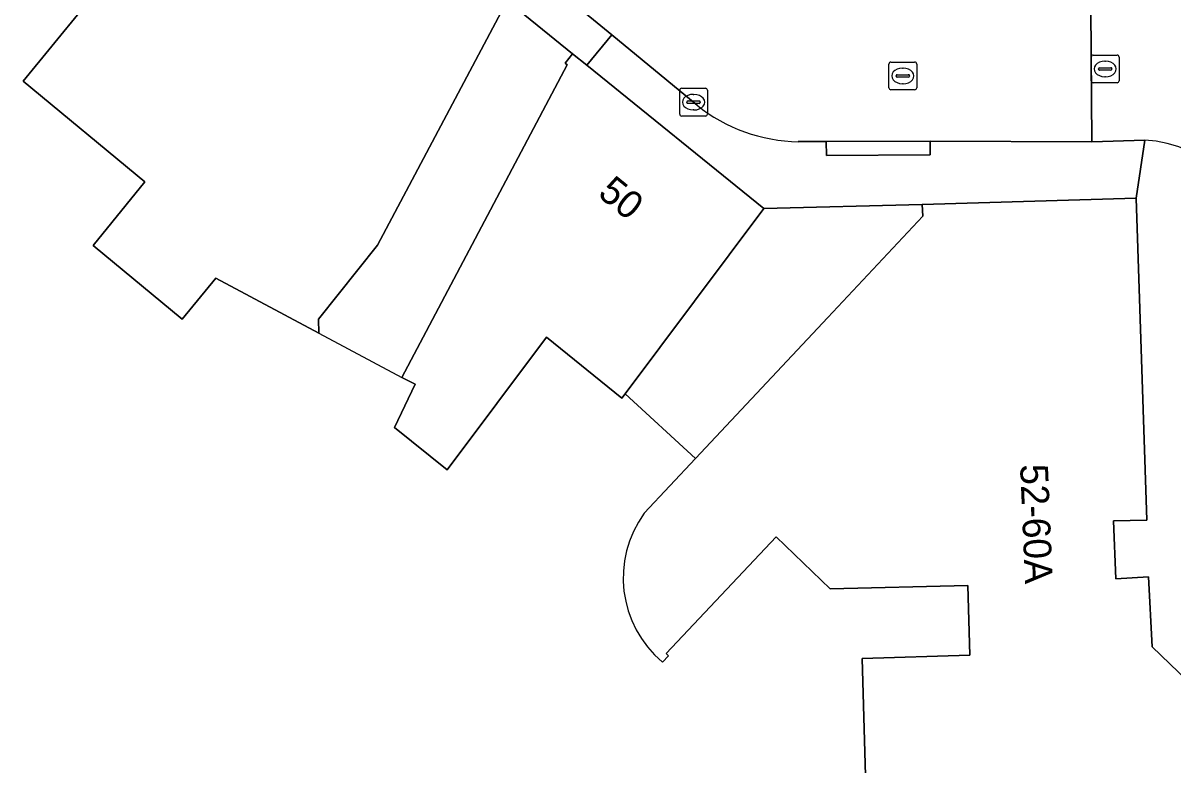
# Model space of a CAD drawing. Extents: x 161881 to 162523, y 381678 to 382381.
# Drawn here: x 162044.54 to 162085.93, y 382190.07 to 382216.77 of the extents above; entities that cross this region are included whole.
import ezdxf

# ---------------------------------------------------------------- set-up
doc = ezdxf.new("R2010")
doc.units = 0
for name, color, linetype in [('IMGEO_Erf', 7, 'Continuous'), ('IMGEO_Kolk', 7, 'Continuous'), ('IMGEO_Pand', 7, 'Continuous'), ('IMGEO_Pand_nummerreeks', 7, 'Continuous'), ('IMGEO_Pand_overbouw', 7, 'Continuous'), ('IMGEO_Rijbaan_lokaal_open', 7, 'Continuous'), ('IMGEO_Rioolput', 7, 'Continuous'), ('IMGEO_Voetpad_open', 7, 'Continuous')]:
    doc.layers.add(name, color=color, linetype=linetype)

msp = doc.modelspace()

# ---------------------------------------------------------------- linework, layer by layer
at = {"layer": 'IMGEO_Erf'}
for points in [[(162066.905, 382199.132), (162068.746, 382201.096), (162073.507, 382206.176), (162076.926, 382209.823), (162076.911, 382210.239), (162071.206, 382210.089), (162066.216, 382203.42), (162066.102, 382203.268), (162063.389, 382205.467), (162059.806, 382200.687), (162057.917, 382202.218), (162058.664, 382203.774), (162058.181, 382204.01), (162064.13, 382215.264), (162064.051, 382215.323), (162064.317, 382215.661), (162061.973, 382217.567), (162057.305, 382208.775), (162055.176, 382206.114), (162055.195, 382205.609), (162051.479, 382207.592), (162050.274, 382206.114), (162047.066, 382208.763), (162048.931, 382211.049), (162044.544, 382214.673), (162047.748, 382218.602)], [(162074.741, 382193.897), (162078.626, 382194.019), (162078.546, 382196.531), (162073.593, 382196.41), (162071.649, 382198.284), (162067.692, 382194.083), (162067.774, 382193.996), (162067.56, 382193.772)], [(162075.168, 382179.155), (162074.741, 382193.897)]]:
    msp.add_lwpolyline(points, dxfattribs=at)
msp.add_arc((162070.096, 382196.802), 3.951, 143.8643, 230.0699, dxfattribs=at)
at = {"layer": 'IMGEO_Kolk'}
for p, q in [((162068.178, 382213.495), (162068.178, 382214.347)), ((162068.253, 382214.421), (162069.105, 382214.421)), ((162069.179, 382214.347), (162069.179, 382213.495)), ((162068.437, 382213.915), (162068.437, 382213.927)), ((162068.875, 382213.878), (162068.477, 382213.878)), ((162068.48, 382213.964), (162068.878, 382213.964)), ((162068.666, 382214.201), (162068.691, 382214.201)), ((162068.921, 382213.927), (162068.921, 382213.915)), ((162069.105, 382213.421), (162068.253, 382213.421)), ((162068.689, 382213.641), (162068.664, 382213.641))]:
    msp.add_line(p, q, dxfattribs=at)
for points in [[(162068.178, 382213.495), (162068.178, 382214.347)], [(162068.253, 382214.421), (162069.105, 382214.421)], [(162069.179, 382214.347), (162069.179, 382213.495)], [(162069.105, 382213.421), (162068.253, 382213.421)]]:
    msp.add_lwpolyline(points, dxfattribs=at)
for centre, radius, start, end in [((162068.255, 382214.345), 0.0765, 91.552, 178.448), ((162068.255, 382214.345), 0.0765, 91.552, 178.448), ((162069.103, 382214.345), 0.0765, 1.552, 88.448), ((162069.103, 382214.345), 0.0765, 1.552, 88.448), ((162068.477, 382213.924), 0.0403, 85.8775, 175.7526), ((162068.474, 382213.914), 0.0366, 178.938, 274.7102), ((162068.878, 382213.921), 0.043, 264.8664, 352.4533), ((162068.882, 382213.926), 0.0386, 1.7309, 96.639), ((162068.255, 382213.497), 0.0765, 181.552, 268.448), ((162068.255, 382213.497), 0.0765, 181.552, 268.448), ((162069.103, 382213.497), 0.0765, 271.552, 358.448), ((162069.103, 382213.497), 0.0765, 271.552, 358.448)]:
    msp.add_arc(centre, radius, start, end, dxfattribs=at)
for centre, major_axis, ratio, start_param, end_param in [((162068.665, 382213.921), (-0.387, 0.002), 0.722429, 4.712389, 7.853982), ((162068.69, 382213.921), (-0.39, 0.002), 0.717154, 1.570796, 4.712389)]:
    msp.add_ellipse(centre, major_axis=major_axis, ratio=ratio, start_param=start_param, end_param=end_param, dxfattribs=at)
at = {"layer": 'IMGEO_Pand'}
for points in [[(162047.748, 382218.602), (162044.544, 382214.673), (162048.931, 382211.049), (162047.066, 382208.763), (162050.274, 382206.114), (162051.479, 382207.592), (162055.195, 382205.609), (162055.176, 382206.114), (162057.305, 382208.775), (162061.973, 382217.567)], [(162085.181, 382194.323), (162085.053, 382196.837), (162083.88, 382196.772), (162083.795, 382198.85), (162084.988, 382198.879), (162084.606, 382210.465), (162076.911, 382210.239), (162076.926, 382209.823), (162073.507, 382206.176), (162068.746, 382201.096), (162066.905, 382199.132)], [(162067.56, 382193.772), (162067.774, 382193.996), (162067.692, 382194.083), (162071.649, 382198.284), (162073.593, 382196.41), (162078.546, 382196.531), (162078.626, 382194.019), (162074.741, 382193.897), (162075.168, 382179.155), (162081.552, 382179.326), (162084.022, 382177.24), (162082.333, 382175.326), (162082.586, 382175.12), (162085.015, 382177.926), (162087.132, 382180.372), (162087.289, 382180.239), (162092.935, 382186.87), (162092.832, 382186.958), (162085.181, 382194.323)]]:
    msp.add_lwpolyline(points, dxfattribs=at)
msp.add_lwpolyline([(162066.216, 382203.42), (162071.206, 382210.089), (162064.838, 382215.251), (162064.317, 382215.661), (162064.051, 382215.323), (162064.13, 382215.264), (162058.181, 382204.01), (162058.664, 382203.774), (162057.917, 382202.218), (162059.806, 382200.687), (162063.389, 382205.467), (162066.102, 382203.268)], close=True, dxfattribs=at)
msp.add_arc((162070.096, 382196.802), 3.951, 143.8643, 230.0699, dxfattribs=at)
at = {"layer": 'IMGEO_Pand_overbouw'}
for points in [[(162055.195, 382205.609), (162058.181, 382204.01), (162064.13, 382215.264), (162064.051, 382215.323), (162064.317, 382215.661), (162061.973, 382217.567), (162057.305, 382208.775), (162055.176, 382206.114)], [(162076.911, 382210.239), (162071.206, 382210.089), (162066.216, 382203.42), (162068.746, 382201.096), (162073.507, 382206.176), (162076.926, 382209.823)]]:
    msp.add_lwpolyline(points, close=True, dxfattribs=at)
at = {"layer": 'IMGEO_Rijbaan_lokaal_open'}
for points in [[(162054.538, 382225.568), (162056.848, 382223.672), (162062.715, 382218.833), (162065.737, 382216.341), (162068.807, 382213.809)], [(162072.445, 382212.5), (162073.456, 382212.504), (162077.189, 382212.519), (162083.011, 382212.494), (162082.973, 382217.297), (162078.27, 382217.266), (162073.189, 382217.224)], [(162084.67, 382217.319), (162084.486, 382217.312), (162082.973, 382217.297), (162083.011, 382212.494), (162084.914, 382212.552)]]:
    msp.add_lwpolyline(points, dxfattribs=at)
for centre, radius, start, end in [((162072.533, 382218.455), 5.956, 231.2695, 269.1517), ((162084.723, 382208.231), 4.325, 2.8897, 87.4722)]:
    msp.add_arc(centre, radius, start, end, dxfattribs=at)
at = {"layer": 'IMGEO_Rioolput'}
for p, q in [((162082.991, 382214.691), (162082.991, 382215.543)), ((162083.066, 382215.617), (162083.918, 382215.617)), ((162083.992, 382215.543), (162083.992, 382214.691)), ((162075.708, 382214.44), (162075.708, 382215.292)), ((162075.783, 382215.366), (162076.635, 382215.366)), ((162076.196, 382215.146), (162076.221, 382215.146)), ((162076.709, 382215.292), (162076.709, 382214.44)), ((162083.25, 382215.111), (162083.25, 382215.123)), ((162083.688, 382215.074), (162083.29, 382215.074)), ((162083.293, 382215.16), (162083.691, 382215.16)), ((162083.479, 382215.397), (162083.504, 382215.397)), ((162083.734, 382215.123), (162083.734, 382215.111)), ((162075.967, 382214.86), (162075.967, 382214.872)), ((162076.405, 382214.823), (162076.007, 382214.823)), ((162076.01, 382214.909), (162076.408, 382214.909)), ((162076.451, 382214.872), (162076.451, 382214.86)), ((162083.502, 382214.837), (162083.477, 382214.837)), ((162076.635, 382214.366), (162075.783, 382214.366)), ((162076.219, 382214.586), (162076.194, 382214.586)), ((162083.918, 382214.617), (162083.066, 382214.617))]:
    msp.add_line(p, q, dxfattribs=at)
for points in [[(162082.991, 382214.691), (162082.991, 382215.543)], [(162083.066, 382215.617), (162083.918, 382215.617)], [(162083.992, 382215.543), (162083.992, 382214.691)], [(162075.708, 382214.44), (162075.708, 382215.292)], [(162075.783, 382215.366), (162076.635, 382215.366)], [(162076.709, 382215.292), (162076.709, 382214.44)], [(162076.635, 382214.366), (162075.783, 382214.366)], [(162083.918, 382214.617), (162083.066, 382214.617)]]:
    msp.add_lwpolyline(points, dxfattribs=at)
for centre, radius, start, end in [((162083.068, 382215.541), 0.0765, 91.552, 178.448), ((162083.068, 382215.541), 0.0765, 91.552, 178.448), ((162083.916, 382215.541), 0.0765, 1.552, 88.448), ((162083.916, 382215.541), 0.0765, 1.552, 88.448), ((162075.785, 382215.29), 0.0765, 91.552, 178.448), ((162075.785, 382215.29), 0.0765, 91.552, 178.448), ((162076.633, 382215.29), 0.0765, 1.552, 88.448), ((162076.633, 382215.29), 0.0765, 1.552, 88.448), ((162083.29, 382215.12), 0.0403, 85.8775, 175.7526), ((162083.287, 382215.11), 0.0366, 178.938, 274.7102), ((162083.691, 382215.117), 0.043, 264.8664, 352.4533), ((162083.695, 382215.122), 0.0386, 1.7309, 96.639), ((162076.007, 382214.869), 0.0403, 85.8775, 175.7526), ((162076.004, 382214.859), 0.0366, 178.938, 274.7102), ((162076.408, 382214.866), 0.043, 264.8664, 352.4533), ((162076.412, 382214.871), 0.0386, 1.7309, 96.639), ((162083.068, 382214.693), 0.0765, 181.552, 268.448), ((162083.068, 382214.693), 0.0765, 181.552, 268.448), ((162083.916, 382214.693), 0.0765, 271.552, 358.448), ((162083.916, 382214.693), 0.0765, 271.552, 358.448), ((162075.785, 382214.442), 0.0765, 181.552, 268.448), ((162075.785, 382214.442), 0.0765, 181.552, 268.448), ((162076.633, 382214.442), 0.0765, 271.552, 358.448), ((162076.633, 382214.442), 0.0765, 271.552, 358.448)]:
    msp.add_arc(centre, radius, start, end, dxfattribs=at)
for centre, major_axis, ratio, start_param, end_param in [((162076.195, 382214.866), (-0.387, 0.002), 0.722429, 4.712389, 7.853982), ((162076.22, 382214.866), (-0.39, 0.002), 0.717154, 1.570796, 4.712389), ((162083.478, 382215.117), (-0.387, 0.002), 0.722429, 4.712389, 7.853982), ((162083.503, 382215.117), (-0.39, 0.002), 0.717154, 1.570796, 4.712389)]:
    msp.add_ellipse(centre, major_axis=major_axis, ratio=ratio, start_param=start_param, end_param=end_param, dxfattribs=at)
at = {"layer": 'IMGEO_Voetpad_open'}
for points in [[(162064.317, 382215.661), (162064.838, 382215.251), (162065.737, 382216.341), (162062.715, 382218.833), (162061.818, 382217.696), (162061.973, 382217.567)], [(162077.189, 382212.519), (162073.456, 382212.504), (162073.457, 382212.006), (162077.19, 382212.02)]]:
    msp.add_lwpolyline(points, close=True, dxfattribs=at)
for points in [[(162068.807, 382213.809), (162065.737, 382216.341), (162064.838, 382215.251), (162071.206, 382210.089), (162076.911, 382210.239), (162084.606, 382210.465), (162084.914, 382212.552)], [(162084.914, 382212.552), (162083.011, 382212.494), (162077.189, 382212.519), (162077.19, 382212.02), (162073.457, 382212.006), (162073.456, 382212.504), (162072.445, 382212.5)], [(162084.914, 382212.552), (162084.606, 382210.465), (162084.988, 382198.879), (162083.795, 382198.85), (162083.88, 382196.772), (162085.053, 382196.837), (162085.181, 382194.323), (162092.832, 382186.958), (162095.504, 382189.989), (162101.353, 382184.848), (162107.416, 382179.84), (162107.127, 382179.509), (162109.213, 382177.62), (162111.309, 382175.703)]]:
    msp.add_lwpolyline(points, dxfattribs=at)
for centre, radius, start, end in [((162072.533, 382218.455), 5.956, 231.2695, 269.1517), ((162084.723, 382208.231), 4.325, 2.8897, 87.4722)]:
    msp.add_arc(centre, radius, start, end, dxfattribs=at)

# ---------------------------------------------------------------- texts
at = {"layer": 'IMGEO_Pand_nummerreeks'}
for s, rotation, p in [('50', 320.859, (162065.191, 382210.566)), ('52-60A', 272.3432, (162080.43, 382200.879))]:
    msp.add_text(s, height=1, rotation=rotation, dxfattribs=at).set_placement(p)

doc.saveas('drawing.dxf')
